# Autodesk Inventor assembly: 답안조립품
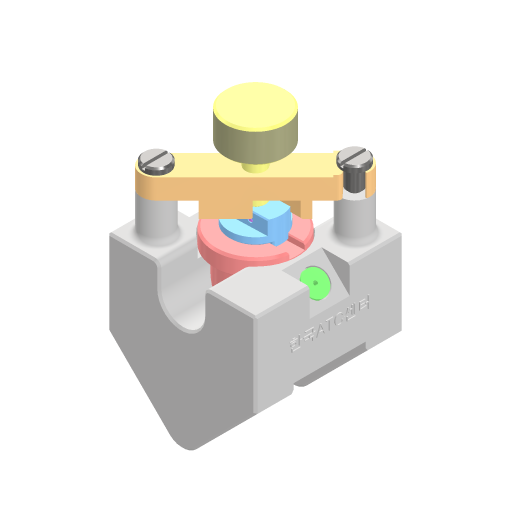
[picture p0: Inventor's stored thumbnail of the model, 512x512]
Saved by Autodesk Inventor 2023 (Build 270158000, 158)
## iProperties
Created: 2025-02
Part Number: 답안조립품
Document SubType Name: Assembly
Designer: home
Author: home
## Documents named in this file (9)
- C:\Users\home\Desktop\750203V1004\답안조립품.iam
- C:\Users\home\Desktop\750203V1004\본체.ipt
- C:\Users\home\Documents\Inventor\가공품.ipt
- C:\Users\home\Desktop\750203V1004\가져온 구성요소\고정핀\고정핀.ipt
- C:\Users\home\Desktop\750203V1004\가져온 구성요소\노브\노브.ipt
- C:\Users\home\Desktop\750203V1004\가져온 구성요소\드릴부시\드릴부시.ipt
- C:\Users\home\Desktop\750203V1004\가져온 구성요소\서포터\서포터.ipt
- C:\Users\home\Desktop\750203V1004\가져온 구성요소\스트리퍼 볼트 M6x10\스트리퍼 볼트 M6x10.ipt
- C:\Users\home\Desktop\750203V1004\가져온 구성요소\조\조.ipt
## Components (2 placed, 2 different names)
1. 가공품:1 — 각도:1
2. 고정핀:1
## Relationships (1: Angle 1)
- 각도:1 [Angle]: 가공품:1
